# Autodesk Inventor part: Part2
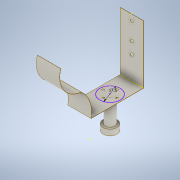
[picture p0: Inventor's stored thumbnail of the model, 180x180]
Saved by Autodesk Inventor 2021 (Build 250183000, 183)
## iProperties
Created: 2023-08
Part Number: Part2
Material: Titanium
Document SubType Name: Modeling
Designer: canad
Density: 4.51 g/cm^3
Appearance: Titanium
Author: canad
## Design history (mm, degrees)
sketch "Sketch1"
  geometry: L1 (0, -360)-(-500, -360); L2 (-500, -360)-(-500, 0); L3 (-500, 0)-(-500, 87.5); L4 (-500, -125)-(-500, -180); A1 r 202.795 centre (-59.409, 156.102) between (0, 350) and (-261.322, 175); A2 r 259.713 centre (-458.617, 343.895) between (-500, 87.5) and (-261.322, 175); 1 further point
  constraints: 8 end point, 4 point on circle, 2 centre point, 1 horizontal, 1 midpoint
  dimensions: "d3" = 500 distance of L1.start L1.end; "d4" = 87.5 distance of L2.end L3.end; "d64" = 360 distance of L1.end L2.end
extrude_surface "ExtrusionSrf1" sketch "Sketch1" dims "d27" = 200, "d28" = 0
sketch "Sketch12"
  geometry: L1 (0, 0)-(200, 0) reference; C1 r 87.5 at (100, 188.913); 1 further point
  constraints: 1 centre point
  dimensions: "d32" = 175 diameter of C1
sketch "Sketch16"
  geometry: 1 further point
sketch "Sketch17"
  geometry: C1 r 40 at (100, 187.325); 1 further point
  constraints: 1 centre point
  dimensions: "d34" = 80 diameter of C1
extrude "Extrusion4" new body sketch "Sketch17" distance "d35" = 250; taper "d36" = 0 deg
sketch "Sketch18"
  geometry: C1 r 40 at (0, 0) reference; 1 further point
sketch "Sketch19"
  geometry: 1 further point
workplane "Work Plane5"
sketch "Sketch20"
  geometry: C1 r 40 at (0, 0) reference; C2 r 60 at (0, 0); 1 further point
  constraints: 1 centre point, 1 coincident
  dimensions: "d39" = 120 diameter of C2
extrude "Extrusion5" join sketch "Sketch20" distance "d40" = 50; taper "d41" = 0 deg
thicken "Thicken1" dims "d42" = 2, "d43" = 2
sketch "Sketch21"
  geometry: L1 (0, -500)-(200, -500) reference; 1 further point
sketch "Sketch22"
  geometry: L1 (0, -500)-(200, -500) reference; L2 (100, -500)-(100, -50); L3 (86.105, -76.733)-(69.901, -51.333); L4 (69.901, -51.333)-(83.796, -24.6); L5 (83.796, -24.6)-(113.895, -23.267); L6 (113.895, -23.267)-(130.099, -48.667); L7 (130.099, -48.667)-(116.204, -75.4); L8 (116.204, -75.4)-(86.105, -76.733); L9 (100, -500)-(100, -200); L10 (79.844, -215.888)-(76.162, -190.488); L11 (76.162, -190.488)-(96.318, -174.6); L12 (96.318, -174.6)-(120.156, -184.112); L13 (120.156, -184.112)-(123.838, -209.512); L14 (123.838, -209.512)-(103.682, -225.4); L15 (103.682, -225.4)-(79.844, -215.888); L16 (100, -500)-(100, -300); L17 (82.809, -321.024)-(73.197, -295.624); L18 (73.197, -295.624)-(90.388, -274.6); L19 (90.388, -274.6)-(117.191, -278.976); L20 (117.191, -278.976)-(126.803, -304.376); L21 (126.803, -304.376)-(109.612, -325.4); L22 (109.612, -325.4)-(82.809, -321.024); C1 r 12.5 at (100, -50); C2 r 12.5 at (100, -200); C3 r 12.5 at (100, -300); 4 further points
  constraints: 42 end point, 6 coincident, 3 centre point, 2 point on line, 1 midpoint, 1 vertical, 39 other
  dimensions: "d45" = 450 distance of L2.start L2.end; "d46" = 300 distance of L2.start L9.end; "d47" = 200 distance of L2.start L16.end; "d48" = 25.4 vertical distance of L5.end L6.end; "d49" = 25.4 vertical distance of L12.end L13.end; "d50" = 25.4 vertical distance of L19.end L20.end; "d51" = 25 diameter of C1; "d52" = 25 diameter of C2; "d53" = 25 diameter of C3
extrude "Extrusion6" cut sketch "Sketch22" distance "d54" = 0.19; taper "d55" = 0 deg
extrude "Extrusion7" cut sketch "Sketch22" stored distance "d56" = 0.19; taper "d57" = 0 deg
sketch "Sketch23"
  geometry: C1 r 10 at (100, -247.325); C2 r 10 at (160.338, -187.325); C3 r 10 at (100, -127); C4 r 10 at (40, -187.325); A1 r 60 centre (100, -187.325) between (100, -247.325) and (40, -187.325) reference; 1 further point
  constraints: 4 centre point, 2 point on circle
  dimensions: "d58" = 20 diameter of C1; "d59" = 20 diameter of C2; "d60" = 20 diameter of C3; "d61" = 20 diameter of C4
extrude "Extrusion8" cut sketch "Sketch23" stored distance "d62" = 0; taper "d63" = 0 deg
body "Solid3"
body "Srf1"
other parameters: "sa_2" = 4, "sa_3" = 2.11291e+07
